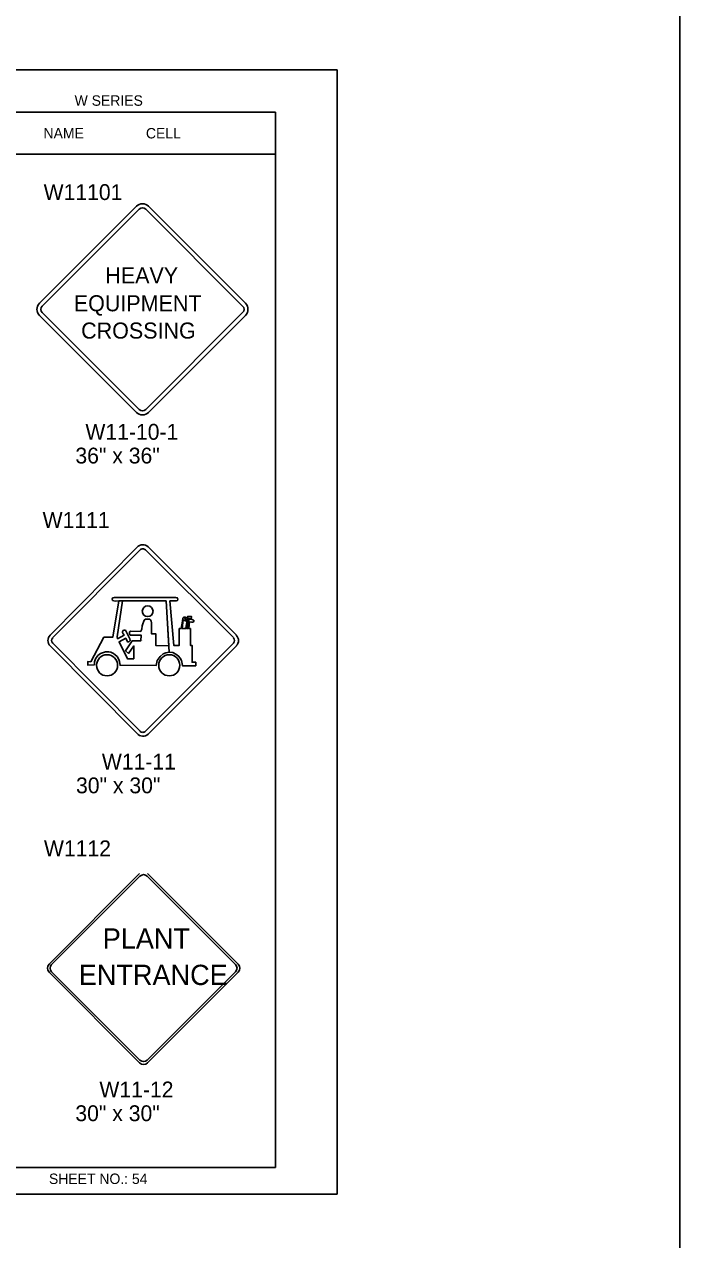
# Model space of a CAD drawing. Extents: x -5299 to 22597, y -19549 to -1808.
# Drawn here: x 4705 to 5202, y -5500 to -4579 of the extents above; entities that cross this region are included whole.
import ezdxf

# ---------------------------------------------------------------- set-up
doc = ezdxf.new("R2010")
doc.units = 0
for name, color, linetype in [('Level 1', 7, 'Continuous'), ('Level 2', 7, 'Continuous'), ('Level 3', 7, 'Continuous'), ('Level 62', 7, 'Continuous')]:
    doc.layers.add(name, color=color, linetype=linetype)

msp = doc.modelspace()

# ---------------------------------------------------------------- linework, layer by layer
at = {"layer": 'Level 1'}
for p, q in [((4895.61, -4645.77), (4288.6, -4645.77)), ((4895.61, -4645.77), (4895.61, -5445.77)), ((4895.61, -4677.44), (4288.6, -4677.44)), ((4789.99, -4717.02), (4716.45, -4790.57)), ((4872.7, -4790.57), (4799.15, -4717.02)), ((4792.12, -4719.14), (4718.57, -4792.69)), ((4792.12, -4719.14), (4792.12, -4719.14)), ((4870.58, -4792.69), (4797.03, -4719.14)), ((4716.45, -4799.73), (4789.99, -4873.28)), ((4718.57, -4797.61), (4792.11, -4871.16)), ((4794.46, -4795.15), (4794.46, -4795.15)), ((4797.03, -4871.15), (4870.58, -4797.61)), ((4799.15, -4873.28), (4872.7, -4799.73)), ((4724.55, -5042.08), (4790.55, -4975.42)), ((4798.91, -4975.2), (4865.79, -5042.08)), ((4726.53, -5044.06), (4792.75, -4977.4)), ((4796.93, -4977.4), (4863.59, -5044.06)), ((4776.6, -5016.19), (4812.53, -5016.18)), ((4812.53, -5016.18), (4812.54, -5016.18)), ((4814.91, -5055.05), (4812.54, -5016.18)), ((4812.54, -5016.18), (4814.91, -5055.05)), ((4825.23, -5029.52), (4824.93, -5031.1)), ((4825.22, -5029.56), (4824.93, -5031.1)), ((4827, -5028.6), (4826.55, -5028.52)), ((4826.55, -5028.52), (4827.67, -5031.24)), ((4827.67, -5031.25), (4826.55, -5028.52)), ((4827, -5028.6), (4826.89, -5028.58)), ((4828.18, -5031.13), (4828.52, -5029.23)), ((4828.52, -5029.23), (4828.26, -5029.08)), ((4828.52, -5029.23), (4828.26, -5029.08)), ((4828.69, -5029.34), (4828.39, -5031.07)), ((4824.11, -5036.31), (4824.11, -5037.19)), ((4824.11, -5036.31), (4824.11, -5037.19)), ((4824.63, -5033.15), (4824.17, -5035.63)), ((4824.6, -5033.27), (4824.17, -5035.62)), ((4824.93, -5031.1), (4824.63, -5033.15)), ((4824.91, -5031.24), (4824.63, -5033.15)), ((4827.67, -5031.24), (4827.17, -5031.27)), ((4792.75, -5114.9), (4726.53, -5048.24)), ((4794.83, -5046.29), (4794.83, -5046.29)), ((4863.59, -5048.24), (4796.93, -5114.9)), ((4790.55, -5116.66), (4724.55, -5050.22)), ((4865.79, -5050.22), (4798.91, -5117.1)), ((4723.69, -5291.63), (4792.44, -5222.88)), ((4798.42, -5222.88), (4867.16, -5291.63)), ((4725.69, -5291.88), (4792.69, -5224.87)), ((4798.17, -5224.87), (4865.17, -5291.88)), ((4792.44, -5366.35), (4723.69, -5297.6)), ((4792.69, -5364.36), (4725.69, -5297.36)), ((4795.28, -5294.91), (4795.28, -5294.91)), ((4865.17, -5297.36), (4798.17, -5364.36)), ((4867.16, -5297.61), (4798.42, -5366.35)), ((4288.6, -5445.77), (4895.61, -5445.77))]:
    msp.add_line(p, q, dxfattribs=at)
for points in [[(4776.6, -5016.19), (4772.01, -5043.71), (4765.38, -5043.71), (4755.39, -5062.27), (4753.15, -5062.06), (4753.15, -5065.02), (4758.15, -5064.61), (4758.15, -5062.27), (4758.86, -5060.02), (4760.8, -5057.58), (4762.63, -5055.95), (4764.36, -5055.44), (4766.61, -5054.93), (4768.95, -5054.82), (4770.69, -5055.13), (4772.52, -5056.05), (4773.95, -5057.07), (4775.37, -5058.29), (4776.6, -5060.53), (4777.11, -5062.16), (4777.41, -5063.59), (4777.72, -5064.92), (4777.62, -5064.92), (4804.94, -5065.22), (4805.76, -5061.25), (4807.9, -5058.39), (4810.24, -5056.35), (4812.28, -5055.44), (4814.91, -5055.05)], [(4824.11, -5037.19), (4822.68, -5037.19), (4822.48, -5037.19), (4822.48, -5049.93), (4818.3, -5049.93), (4815.34, -5016.19), (4818.11, -5016.21), (4819.04, -5016.23), (4820.16, -5016.23), (4821.05, -5015.98), (4821.46, -5014.92), (4820.99, -5013.82), (4819.98, -5013.65), (4818.78, -5013.62), (4773.13, -5013.64), (4772.01, -5013.94), (4771.6, -5014.66), (4771.91, -5015.78), (4773.82, -5016.27), (4776.6, -5016.19)], [(4812.54, -5016.18), (4814.63, -5050.34), (4804.84, -5050.03), (4804.84, -5041.16), (4801.37, -5041.06), (4801.47, -5032.9), (4801.07, -5031.58), (4800.56, -5030.66), (4799.94, -5030.15), (4799.33, -5030.05), (4798.62, -5030.05), (4797.8, -5030.05), (4797.19, -5030.15), (4796.78, -5030.15), (4795.87, -5030.87), (4795.56, -5031.48), (4795.25, -5032.19), (4795.15, -5032.7), (4794.34, -5035.05), (4794.03, -5037.59), (4793.42, -5039.12), (4793.42, -5039.33), (4785.67, -5039.02), (4784.75, -5039.74), (4784.65, -5040.76), (4784.65, -5041.26), (4785.26, -5042.08), (4793.62, -5042.18), (4793.32, -5046.57), (4786.79, -5046.46), (4781.8, -5054.01), (4783.94, -5055.95), (4788.12, -5050.34), (4787.91, -5060.02), (4783.22, -5060.02), (4776.9, -5047.18), (4781.9, -5044.53), (4783.33, -5047.28), (4784.35, -5047.18), (4785.37, -5046.26), (4784.96, -5044.93), (4781.59, -5038.41), (4780.78, -5038.31), (4779.96, -5038.61), (4779.55, -5039.53), (4779.55, -5040.25), (4780.06, -5041.16), (4780.57, -5042.18), (4775.68, -5044.83), (4775.27, -5043.41), (4779.45, -5016.19)], [(4779.45, -5016.19), (4812.54, -5016.18)], [(4824.72, -5037.19), (4825.53, -5030.46), (4826.03, -5030.77)], [(4824.72, -5037.19), (4825.53, -5030.46), (4826.03, -5030.77)], [(4826.21, -5028.52), (4825.84, -5028.52), (4825.33, -5029.03), (4825.23, -5029.52)], [(4826.55, -5028.52), (4825.84, -5028.52), (4825.33, -5029.03), (4825.23, -5029.52)], [(4829.69, -5031.54), (4829.09, -5037.18), (4828.02, -5037.18), (4829.2, -5029.23), (4831.45, -5029.74), (4831.65, -5028.01), (4828.9, -5028.01), (4828.69, -5029.34)], [(4829.69, -5031.54), (4829.09, -5037.18), (4828.02, -5037.18), (4829.2, -5029.23), (4831.45, -5029.74), (4831.65, -5028.01), (4828.9, -5028.01), (4828.69, -5029.34)], [(4831.92, -5030.18), (4831.85, -5030.15), (4831.34, -5030.15), (4830.63, -5030.15), (4830.53, -5030.15), (4830.12, -5030.56), (4829.82, -5030.87), (4829.78, -5031.02)], [(4832.2, -5030.31), (4831.85, -5030.15), (4831.34, -5030.15), (4830.63, -5030.15), (4830.53, -5030.15), (4830.12, -5030.56), (4829.82, -5030.87), (4829.78, -5031.02)], [(4831.79, -5032.3), (4832.67, -5032.4), (4833.49, -5031.89), (4833.59, -5031), (4833.08, -5030.66)], [(4832.8, -5030.55), (4832.57, -5030.46), (4832.2, -5030.31)], [(4833.08, -5030.66), (4832.57, -5030.46), (4832.2, -5030.31)], [(4833.59, -5031), (4833.59, -5030.97), (4833.34, -5030.82)], [(4828.39, -5031.07), (4827.37, -5036.98), (4827.37, -5037.19), (4824.72, -5037.19)], [(4826.7, -5031.1), (4827.16, -5031.27), (4827.17, -5031.27)], [(4826.7, -5031.1), (4827.16, -5031.27), (4827.67, -5031.25)], [(4835.12, -5065.43), (4835.01, -5062.67), (4832.26, -5062.67), (4832.36, -5050.03), (4830.94, -5049.93), (4830.94, -5037.18), (4829.82, -5037.18), (4830.22, -5032.09), (4831.71, -5032.29)], [(4835.12, -5065.43), (4835.01, -5062.67), (4832.26, -5062.67), (4832.36, -5050.03), (4830.94, -5049.93), (4830.94, -5037.18), (4829.82, -5037.18), (4830.22, -5032.09), (4831.71, -5032.29)], [(4831.79, -5032.3), (4832.67, -5032.4), (4833.49, -5031.89), (4833.51, -5031.74)], [(4814.91, -5055.05), (4815.03, -5055.03), (4817.58, -5055.33), (4819.93, -5056.46), (4821.97, -5057.98), (4823.29, -5059.62), (4824.21, -5061.35), (4824.41, -5062.57), (4824.72, -5063.69), (4824.92, -5065.32), (4835.12, -5065.43)]]:
    msp.add_lwpolyline(points, dxfattribs=at)
for centre, radius in [((4798.52, -5024.04), 4.06), ((4767.73, -5065.02), 7.98), ((4814.93, -5065.02), 7.98)]:
    msp.add_circle(centre, radius, dxfattribs=at)
for centre, radius, start, end in [((4794.57, -4721.6), 6.48, 45, 135), ((4794.57, -4721.6), 3.48, 45, 135), ((4721.03, -4795.15), 6.48, 135, 225), ((4868.12, -4795.15), 6.48, 315, 45), ((4721.03, -4795.15), 3.48, 135, 225), ((4868.12, -4795.15), 3.48, 315, 45), ((4794.57, -4868.7), 6.48, 225, 315), ((4794.57, -4868.7), 3.48, 225, 315), ((4794.81, -4979.54), 5.89, 46.2557, 136.75917), ((4794.81, -4979.56), 2.94, 44.74826, 135.25174), ((4828.92, -5030.26), 3.76, 168.69007, 169.38034), ((4828.02, -5027.58), 3.76, 237.99462, 249.44396), ((4828.02, -5027.58), 3.76, 237.99462, 249.44396), ((4826.21, -5032.28), 3.76, 79.69515, 90), ((4826.33, -5032.3), 3.76, 59.03625, 79.69515), ((4826.33, -5032.3), 3.76, 59.03625, 79.69515), ((4833.6, -5026.82), 3.76, 243.43495, 248.19859), ((4831.4, -5034.04), 3.76, 59.03625, 68.19859), ((4827.87, -5036.31), 3.76, 169.50852, 179.996), ((4827.87, -5036.31), 3.76, 169.5526, 179.996), ((4820.9, -5032.59), 3.76, 349.50852, 351.46923), ((4828.63, -5031.8), 3.76, 169.38034, 171.46923), ((4827.17, -5027.51), 3.76, 270, 285.70573), ((4827.17, -5027.51), 3.76, 270, 285.70573), ((4833.43, -5031.93), 3.76, 165.96375, 173.99), ((4833.43, -5031.93), 3.76, 165.96375, 173.99), ((4832.21, -5028.56), 3.76, 262.40536, 263.65981), ((4832.21, -5028.56), 3.76, 262.40536, 263.65981), ((4829.82, -5031), 3.76, 348.69007, 360), ((4728.6, -5046.23), 5.76, 135.03806, 224.96193), ((4728.6, -5046.23), 2.96, 135.03806, 224.96193), ((4861.44, -5046.23), 2.98, 315.49388, 44.50612), ((4861.62, -5046.23), 5.81, 315.49388, 44.50612), ((4794.92, -5112.9), 5.84, 221.19023, 312.78419), ((4794.81, -5112.95), 2.92, 224.20302, 315.79698), ((4795.43, -5227.61), 3.87, 45, 135), ((4726.68, -5294.62), 4.23, 135, 225), ((4728.43, -5294.62), 3.87, 135, 225), ((4862.43, -5294.62), 3.87, 315, 45), ((4864.18, -5294.62), 4.23, 315, 45), ((4795.43, -5363.36), 4.23, 225, 315), ((4795.43, -5361.62), 3.87, 225, 315)]:
    msp.add_arc(centre, radius, start, end, dxfattribs=at)
at = {"layer": 'Level 3'}
msp.add_line((5202.09, -1877.72), (5202.09, -9425.73), dxfattribs=at)
at = {"layer": 'Level 62'}
msp.add_lwpolyline([(4241.09, -5465.96), (4942.14, -5465.96), (4942.14, -4613.58), (4241.09, -4613.58)], close=True, dxfattribs=at)

# ---------------------------------------------------------------- texts
at = {"layer": 'Level 1'}
for s, height, p in [('HEAVY', 12.187, (4766.39, -4775.46)), ('EQUIPMENT', 12.187, (4742.5, -4796.64)), ('CROSSING', 12.187, (4748.06, -4817.34)), ('PLANT', 15.363, (4764.44, -5279.81)), ('ENTRANCE', 15.363, (4746.26, -5307.4))]:
    msp.add_text(s, height=height, dxfattribs=at).set_placement(p)
at = {"layer": 'Level 2'}
for s, p in [('W11101', (4719.59, -4712.27)), ('W1111', (4718.84, -4960.87)), ('W1112', (4719.84, -5209.77))]:
    msp.add_text(s, height=12, dxfattribs=at).set_placement(p)
at = {"layer": 'Level 3'}
for s, height, p in [('W SERIES', 7.918, (4743.11, -4640.82)), ('NAME', 7.918, (4719.51, -4665.6)), ('CELL', 7.918, (4797.22, -4665.6)), ('W11-10-1', 12, (4751.3, -4894.02)), ('36" x 36"', 12, (4743.7, -4912.02)), ('W11-11', 12, (4763.78, -5144.05)), ('30" x 30"', 12, (4744.18, -5162.05)), ('W11-12', 12, (4761.91, -5392.61)), ('30" x 30"', 12, (4743.67, -5410.61)), ('SHEET NO.: 54', 7.918, (4723.65, -5458.26))]:
    msp.add_text(s, height=height, dxfattribs=at).set_placement(p)

doc.saveas('drawing.dxf')
